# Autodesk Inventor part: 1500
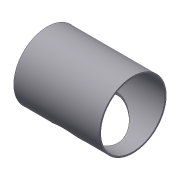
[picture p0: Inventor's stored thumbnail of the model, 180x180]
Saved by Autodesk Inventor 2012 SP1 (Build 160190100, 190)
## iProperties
Created: 2012-02
Part Number: 1500
Material: Aluminum-6061
Document SubType Name: Modeling
Designer: LACO
Density: 2.71 g/cm^3
Mass: 849.444 g
Surface Area: 1877.12 cm^2
Volume: 313.448 cm^3
Author: LACO
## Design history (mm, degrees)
derived "4347K411.ipt"
sketch "Sketch1"
  geometry: C1 r 84.138 at (0, 0) reference; C2 r 80.734 at (0, 0) reference
extrude "Extrusion1" cut sketch "Sketch1" distance "d1" = 88.9; taper "d2" = 0 deg
sketch "Sketch2"
  geometry: L1 (-63.5, 80.734)-(-63.5, -80.734) reference; L2 (152.4, 80.734)-(152.4, -80.734) reference; L3 (-63.5, 0)-(152.4, 0); C1 r 69.85 at (44.45, 0); 2 further points
  constraints: 3 midpoint, 2 end point, 1 centre point, 1 coincident
  dimensions: "d3" = 139.7 diameter of C1
extrude "Extrusion2" cut sketch "Sketch2" stored distance "d5" = 25.4; taper "d6" = 0 deg
feature "NONE::4347K411.ipt" dims "d0" = 10
tag "TaggingFeature1"
body "Solid1"
